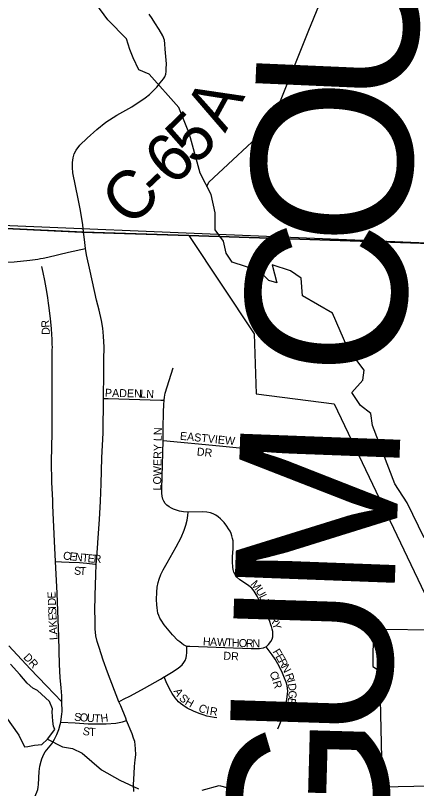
# Model space of a CAD drawing. Extents: x 0 to 34, y 0 to 22.
# Drawn here: x 28.055 to 28.529, y 17.603 to 18.518 of the extents above; entities that cross this region are included whole.
import ezdxf

# ---------------------------------------------------------------- set-up
doc = ezdxf.new("R2010")
doc.units = 0
for name, color, linetype in [('GM_X_Adjacent_County_Text', 7, 'Continuous'), ('GM_X_City_Street', 7, 'Continuous'), ('GM_X_City_Street_Text', 7, 'Continuous'), ('GM_X_Corporation', 7, 'Continuous'), ('GM_X_County_Road', 7, 'Continuous'), ('GM_X_County_Road_Text', 7, 'Continuous'), ('GM_X_Minor_Lake', 7, 'Continuous'), ('GM_X_Minor_River', 7, 'Continuous'), ('GM_X_Section', 7, 'Continuous'), ('GM_X_Township', 7, 'Continuous')]:
    doc.layers.add(name, color=color, linetype=linetype)

msp = doc.modelspace()

# ---------------------------------------------------------------- linework, layer by layer
at = {"layer": 'GM_X_City_Street'}
for points in [[(27.85393, 18.26885), (27.85999, 18.26259), (27.86684, 18.25642), (27.8741, 18.25072), (27.88171, 18.24549), (27.8896, 18.24071), (27.89778, 18.23644), (27.90626, 18.23284), (27.91499, 18.22991), (27.92391, 18.22763), (27.93299, 18.22608), (27.94524, 18.22494), (27.96066, 18.22431), (27.9792, 18.22428), (28.01942, 18.22523), (28.03796, 18.22566), (28.05337, 18.22652), (28.0718, 18.22836), (28.0813, 18.22968), (28.08427, 18.23019), (28.08748, 18.23074), (28.09309, 18.23181), (28.1176, 18.23769), (28.13753, 18.24213)], [(28.13753, 18.24213), (28.13658, 18.25279), (28.13559, 18.25882), (28.13528, 18.2617), (28.13525, 18.26196)], [(28.1591, 18.06485), (28.15953, 18.09534), (28.15934, 18.11085), (28.15974, 18.12537), (28.15893, 18.13859), (28.15799, 18.14787), (28.15656, 18.157), (28.15384, 18.16906), (28.15076, 18.18108), (28.14329, 18.21545), (28.13871, 18.2345), (28.13753, 18.24213)], [(28.10223, 17.87166), (28.10111, 17.89576), (28.09914, 17.93789), (28.09898, 17.94406), (28.0979, 17.96572), (28.09748, 17.99015), (28.09807, 18.02394), (28.09809, 18.05482), (28.0982, 18.08581), (28.09804, 18.10076), (28.09832, 18.11939), (28.09835, 18.12246), (28.09842, 18.12546), (28.09837, 18.12854), (28.09812, 18.13469), (28.09725, 18.14707), (28.09606, 18.1594), (28.0943, 18.17461), (28.09392, 18.17766), (28.09346, 18.18065), (28.09307, 18.18368), (28.09261, 18.18665), (28.09119, 18.1956), (28.08941, 18.20449), (28.08753, 18.21364), (28.08613, 18.22077)], [(28.23069, 18.06269), (28.23126, 18.06636), (28.23209, 18.07086), (28.24146, 18.1011)], [(28.15047, 17.86851), (28.15069, 17.87214), (28.15174, 17.88763), (28.15262, 17.9), (28.15415, 17.92162), (28.15551, 17.9433), (28.15623, 17.96383), (28.15704, 17.99457), (28.15852, 18.02397), (28.1591, 18.06485)], [(28.1591, 18.06485), (28.16459, 18.06469), (28.22689, 18.0628), (28.23069, 18.06269)], [(28.22962, 18.01486), (28.22951, 18.02921), (28.23008, 18.04908), (28.23022, 18.05707), (28.23069, 18.06269)], [(28.25908, 17.93036), (28.25355, 17.93074), (28.24896, 17.93143), (28.24543, 17.9325), (28.2419, 17.93366), (28.23929, 17.93473), (28.2366, 17.93642), (28.23407, 17.93834), (28.232, 17.94041), (28.23038, 17.94302), (28.22923, 17.94554), (28.22859, 17.94915), (28.22812, 17.95265), (28.22799, 17.95783), (28.22962, 18.01486)], [(28.22962, 18.01486), (28.29644, 18.00867), (28.31193, 18.00729), (28.3273, 18.00563), (28.33336, 18.00471), (28.33749, 18.00352), (28.34191, 18.0018), (28.34388, 18.00136), (28.34606, 18.00109), (28.34775, 18.00141), (28.34882, 18.00203), (28.3496, 18.00285), (28.35008, 18.00392), (28.35023, 18.0049), (28.35001, 18.00591), (28.34983, 18.00634), (28.34941, 18.00687), (28.34854, 18.0075), (28.34713, 18.00797), (28.34533, 18.00809), (28.34343, 18.00793), (28.34142, 18.00749), (28.33912, 18.00656)], [(28.25768, 17.77141), (28.25535, 17.77232), (28.25363, 17.77323), (28.25162, 17.77473), (28.24932, 17.77656), (28.24707, 17.77853), (28.24064, 17.78511), (28.23257, 17.7946), (28.23067, 17.79706), (28.2272, 17.80222), (28.22572, 17.80495), (28.22447, 17.80778), (28.22344, 17.8107), (28.22277, 17.81373), (28.22232, 17.8168), (28.22192, 17.82071), (28.22165, 17.82691), (28.22203, 17.83539), (28.22256, 17.84157), (28.22358, 17.847), (28.22479, 17.85085), (28.22692, 17.85641), (28.22977, 17.86195), (28.23443, 17.87005), (28.24503, 17.88911), (28.25071, 17.90019), (28.25441, 17.90875), (28.2564, 17.91465), (28.25787, 17.9207), (28.2587, 17.92613), (28.25908, 17.93036)], [(28.35141, 17.7707), (28.3541, 17.77351), (28.35715, 17.77712), (28.35845, 17.77988), (28.35923, 17.7828), (28.35955, 17.78556), (28.35919, 17.78888), (28.3587, 17.79192), (28.35795, 17.79491), (28.35709, 17.79704), (28.35581, 17.80065), (28.35063, 17.81166), (28.34926, 17.81439), (28.34066, 17.83075), (28.33713, 17.83669), (28.3344, 17.84007), (28.33102, 17.84303), (28.32592, 17.84654), (28.32045, 17.8501), (28.3169, 17.8531), (28.31473, 17.85652), (28.31335, 17.85926), (28.31248, 17.86221), (28.31195, 17.86526), (28.31154, 17.87143), (28.31164, 17.87762), (28.31235, 17.88686), (28.31248, 17.89301), (28.31227, 17.89608), (28.31177, 17.89911), (28.31099, 17.90209), (28.30997, 17.90499), (28.30873, 17.90782), (28.30707, 17.91057), (28.30502, 17.91369), (28.30159, 17.91799), (28.29739, 17.92228), (28.29481, 17.92454), (28.29191, 17.92648), (28.2888, 17.92808), (28.28568, 17.92938), (28.28106, 17.93035), (28.27622, 17.93053), (28.25908, 17.93036)], [(28.10223, 17.87166), (28.10908, 17.8714), (28.11843, 17.87109), (28.13072, 17.87057), (28.1392, 17.86982), (28.14916, 17.86866), (28.15047, 17.86851)], [(28.10966, 17.70563), (28.10946, 17.71303), (28.10895, 17.72232), (28.1078, 17.73456), (28.1069, 17.74981), (28.10593, 17.78256), (28.10394, 17.83426), (28.10223, 17.87166)], [(28.17724, 17.70583), (28.16383, 17.74068), (28.1586, 17.75523), (28.1539, 17.76996), (28.15164, 17.7772), (28.15003, 17.78394), (28.14922, 17.79203), (28.14895, 17.8039), (28.1487, 17.81312), (28.14917, 17.83177), (28.14976, 17.85622), (28.15047, 17.86851)], [(28.04689, 17.77203), (28.0723, 17.7449), (28.09152, 17.72464), (28.10966, 17.70563)], [(28.23074, 17.73517), (28.23161, 17.73565), (28.23958, 17.74041), (28.24734, 17.74558), (28.24977, 17.74752), (28.25198, 17.74969), (28.2539, 17.75212), (28.25545, 17.7548), (28.25661, 17.75767), (28.25736, 17.76069), (28.25769, 17.76374), (28.25756, 17.76679), (28.25768, 17.77141)], [(28.35141, 17.7707), (28.34809, 17.76927), (28.3435, 17.76832), (28.33354, 17.76848), (28.26102, 17.77111), (28.25768, 17.77141)], [(28.36511, 17.67368), (28.3677, 17.67927), (28.3696, 17.68465), (28.37119, 17.69003), (28.3734, 17.69777), (28.37545, 17.70616), (28.3764, 17.7117), (28.37688, 17.71518), (28.37703, 17.71834), (28.37688, 17.7215), (28.37624, 17.72498), (28.37498, 17.7291), (28.37327, 17.73371), (28.37099, 17.73954), (28.36689, 17.74796), (28.36218, 17.75606), (28.35866, 17.76122), (28.35141, 17.7707)], [(28.17724, 17.70583), (28.1828, 17.70873), (28.19105, 17.71305), (28.20735, 17.72206), (28.22623, 17.73269), (28.23074, 17.73517)], [(28.29322, 17.68689), (28.28999, 17.68732), (28.28563, 17.68812), (28.28138, 17.68899), (28.27707, 17.69034), (28.27207, 17.69196), (28.26535, 17.69459), (28.25816, 17.69828), (28.25266, 17.70184), (28.25018, 17.70372), (28.24786, 17.70579), (28.24572, 17.70804), (28.24374, 17.71046), (28.24026, 17.71564), (28.23722, 17.72108), (28.23331, 17.72958), (28.23074, 17.73517)], [(28.10836, 17.68164), (28.10902, 17.68507), (28.10977, 17.69129), (28.10988, 17.69442), (28.10966, 17.70563)], [(28.18636, 17.68384), (28.18522, 17.68657), (28.17933, 17.70094), (28.17724, 17.70583)], [(28.10836, 17.68164), (28.12548, 17.68075), (28.14071, 17.6798), (28.1555, 17.67957), (28.16208, 17.67992), (28.1736, 17.68055), (28.18126, 17.68207), (28.18509, 17.6834), (28.18636, 17.68384)], [(28.1948, 17.59947), (28.19439, 17.60772), (28.19521, 17.62113), (28.19576, 17.62935), (28.19658, 17.63702), (28.19713, 17.64317), (28.19699, 17.65002), (28.19658, 17.65481), (28.1959, 17.65892), (28.19465, 17.66293), (28.19303, 17.66795), (28.18636, 17.68384)], [(28.07178, 17.58311), (28.07451, 17.58769), (28.07636, 17.59097), (28.07876, 17.59615), (28.08008, 17.59897), (28.0811, 17.60192), (28.08181, 17.60495), (28.08217, 17.60803), (28.08297, 17.62338), (28.08373, 17.62944), (28.08501, 17.63543), (28.08591, 17.63834), (28.08703, 17.64116), (28.08841, 17.64386), (28.09005, 17.64643), (28.09382, 17.65128), (28.09768, 17.65622), (28.10103, 17.6615), (28.10387, 17.66708), (28.10611, 17.67292), (28.10784, 17.67893), (28.10836, 17.68164)]]:
    msp.add_lwpolyline(points, dxfattribs=at)
at = {"layer": 'GM_X_Corporation'}
msp.add_lwpolyline([(27.50706, 18.06564), (27.60948, 18.06256), (27.61116, 18.12049), (27.61116, 18.15798), (27.60564, 18.15628), (27.60565, 18.18117), (27.60524, 18.20728), (27.61083, 18.20833), (27.60953, 18.28012), (28.03523, 18.26605), (28.13337, 18.26149), (28.25997, 18.25738), (28.33724, 18.14128), (28.33966, 18.07033), (28.43214, 18.05835), (28.55968, 17.79037), (28.47825, 17.79119), (28.47781, 17.74759), (28.48568, 17.74233), (28.48869, 17.60507), (28.54513, 17.60631)], dxfattribs=at)
msp.add_lwpolyline([(27.50706, 18.06564), (27.60948, 18.06256), (27.61116, 18.12049), (27.61116, 18.15798), (27.60564, 18.15628), (27.60565, 18.18117), (27.60524, 18.20728), (27.61083, 18.20833), (27.60953, 18.28012), (28.03523, 18.26605), (28.13337, 18.26149), (28.25997, 18.25738), (28.33724, 18.14128), (28.33966, 18.07033), (28.43214, 18.05835), (28.55968, 17.79037), (28.47825, 17.79119), (28.47781, 17.74759), (28.48568, 17.74233), (28.48869, 17.60507), (28.54513, 17.60631)], dxfattribs=at)
at = {"layer": 'GM_X_County_Road'}
msp.add_lwpolyline([(28.13525, 18.26196), (28.13436, 18.27016), (28.13193, 18.28716), (28.12897, 18.30091), (28.12276, 18.33165), (28.12225, 18.33788), (28.12223, 18.34406), (28.12303, 18.34945), (28.12438, 18.35404), (28.12654, 18.35862), (28.13085, 18.36455), (28.13948, 18.37292), (28.1509, 18.38282), (28.16187, 18.39153), (28.17481, 18.39988), (28.19262, 18.40986), (28.20847, 18.42055), (28.21328, 18.42449), (28.21781, 18.42873), (28.22207, 18.43325), (28.22602, 18.43802), (28.22989, 18.44288), (28.23158, 18.44542), (28.23254, 18.44833), (28.233, 18.45144), (28.23325, 18.4546), (28.23342, 18.4608), (28.23199, 18.4781), (28.23172, 18.4843), (28.23118, 18.48888), (28.22929, 18.49401), (28.22472, 18.50133), (28.21975, 18.50911), (28.21645, 18.51432), (28.21313, 18.51954)], dxfattribs=at)
at = {"layer": 'GM_X_Minor_Lake'}
for points in [[(27.99403, 17.81025), (27.99061, 17.8125), (27.99142, 17.8053), (27.99374, 17.79924), (27.99454, 17.79355), (27.99385, 17.78482), (27.99051, 17.77568), (27.98792, 17.76769), (27.9846, 17.7559), (27.98197, 17.75246), (27.98578, 17.74945), (27.99074, 17.74493), (27.99799, 17.73815), (28.00866, 17.73101), (28.02012, 17.71781), (28.02814, 17.71066), (28.03428, 17.70007), (28.04347, 17.68799), (28.05879, 17.66646), (28.06533, 17.65246), (28.0695, 17.65287), (28.07745, 17.65444), (28.08615, 17.65527), (28.09255, 17.66176)], [(28.09255, 17.66176), (28.10156, 17.67284), (28.09963, 17.677), (28.09883, 17.68307), (28.09837, 17.69407), (28.09872, 17.69749), (28.09524, 17.7062), (28.08075, 17.719), (28.07542, 17.722), (28.06855, 17.72803), (28.06014, 17.73822), (28.04906, 17.75028)]]:
    msp.add_lwpolyline(points, dxfattribs=at)
at = {"layer": 'GM_X_Minor_River'}
for points in [[(28.28141, 18.31548), (28.28379, 18.32071), (28.35758, 18.38937), (28.40179, 18.50055), (28.42577, 18.55844), (28.43448, 18.59303), (28.44447, 18.61437), (28.45565, 18.62928), (28.46299, 18.65059), (28.46857, 18.695), (28.48617, 18.71225), (28.53638, 18.75754), (28.57229, 18.79508), (28.58827, 18.82217), (28.61736, 18.86153), (28.63021, 18.89845), (28.6331, 18.91061), (28.63749, 18.92468)], [(28.53832, 17.89997), (28.51821, 17.94108), (28.50359, 17.96367), (28.47713, 18.03277), (28.47547, 18.04678), (28.46326, 18.0565), (28.45288, 18.07193), (28.46597, 18.08648), (28.46736, 18.09825), (28.44817, 18.12382), (28.42995, 18.16571), (28.39455, 18.18618), (28.39281, 18.20701), (28.38024, 18.2156), (28.3586, 18.22294), (28.36412, 18.2014), (28.35463, 18.20433), (28.34279, 18.21595), (28.31128, 18.22584), (28.30398, 18.23676), (28.3008, 18.25075), (28.2912, 18.2643), (28.29099, 18.28439), (28.28622, 18.30595), (28.27347, 18.33121), (28.26087, 18.37733), (28.24805, 18.40904), (28.21283, 18.44847), (28.20067, 18.45364), (28.19409, 18.4676), (28.1902, 18.47779), (28.18628, 18.49026), (28.1641, 18.51277), (28.13992, 18.54587)], [(28.09255, 17.66176), (28.11043, 17.6524), (28.12219, 17.65059), (28.1336, 17.64497), (28.15648, 17.6254), (28.17818, 17.61303), (28.20023, 17.60293)], [(28.27565, 17.60119), (28.29569, 17.60665), (28.31544, 17.60148)]]:
    msp.add_lwpolyline(points, dxfattribs=at)
at = {"layer": 'GM_X_Section'}
msp.add_lwpolyline([(28.70052, 19.24223), (28.6651, 18.24345), (27.6773, 18.28453), (27.70209, 19.27644)], close=True, dxfattribs=at)
at = {"layer": 'GM_X_Township'}
for points in [[(26.64338, 18.32213), (26.64994, 18.32195), (26.65415, 18.32164), (26.6574, 18.3212), (26.66046, 18.32066), (26.66345, 18.31987), (26.93903, 18.30939), (27.3097, 18.29835), (27.60273, 18.28017), (27.85085, 18.27245), (28.03523, 18.26605), (28.13527, 18.2617), (28.25997, 18.25738), (28.66555, 18.2443), (28.72626, 19.93416)], [(28.59551, 16.41415), (28.59908, 16.58872), (28.59988, 16.61088), (28.63677, 17.49807), (28.63701, 17.50604), (28.6433, 17.85758), (28.66555, 18.2443), (28.25997, 18.25738), (28.13527, 18.2617), (28.03523, 18.26605), (27.85085, 18.27245), (27.60273, 18.28017), (27.3097, 18.29835), (26.93903, 18.30939), (26.66345, 18.31987), (26.66046, 18.32066), (26.6574, 18.3212), (26.65415, 18.32164), (26.64994, 18.32195), (26.64338, 18.32213)]]:
    msp.add_lwpolyline(points, dxfattribs=at)

# ---------------------------------------------------------------- texts
at = {"layer": 'GM_X_Adjacent_County_Text'}
for s, rotation, p in [('U', 87.49603, (28.52715, 18.41001)), ('O', 87.49603, (28.51983, 18.24267)), ('C', 87.50756, (28.51312, 18.08866)), ('M', 87.82797, (28.5029, 17.82581)), ('U', 88.17612, (28.49758, 17.6587)), ('G', 88.38934, (28.49288, 17.49145))]:
    msp.add_text(s, height=0.18939, rotation=rotation, dxfattribs=at).set_placement(p)
at = {"layer": 'GM_X_City_Street_Text'}
for s, rotation, p in [('R', 94.28275, (28.09519, 18.14889)), ('D', 91.52986, (28.09543, 18.14007)), ('PADEN', 358.75525, (28.16059, 18.06675)), ('LN', 356.98842, (28.20231, 18.06591)), ('LOWERY LN', 89.28359, (28.2271, 17.95586)), ('EASTVIEW', 354.36928, (28.24906, 18.01594)), ('DR', 353.98201, (28.26905, 17.99741)), ('C', 353.84483, (28.11075, 17.87427)), ('E', 353.82939, (28.1182, 17.87347)), ('N', 353.82395, (28.12483, 17.87275)), ('T', 353.86861, (28.13312, 17.87185)), ('E', 354.09465, (28.13979, 17.87114)), ('R', 358.15181, (28.14715, 17.8704)), ('S', 356.69289, (28.12386, 17.85635)), ('T', 357.06235, (28.13059, 17.85596)), ('M', 309.81491, (28.33249, 17.84477)), ('U', 299.94013, (28.33864, 17.83744)), ('E', 92.2404, (28.10239, 17.82819)), ('L', 296.27174, (28.34272, 17.83036)), ('D', 92.57975, (28.10276, 17.81988)), ('L', 294.5615, (28.33167, 17.81739)), ('B', 295.93522, (28.34567, 17.8244)), ('E', 295.84401, (28.34895, 17.81766)), ('I', 92.59392, (28.10295, 17.81572)), ('S', 92.56641, (28.10325, 17.80905)), ('N', 295.72377, (28.33452, 17.81114)), ('R', 295.89831, (28.35186, 17.81165)), ('E', 92.56908, (28.10355, 17.8024)), ('K', 92.57975, (28.10393, 17.79407)), ('R', 295.89831, (28.35513, 17.8049)), ('A', 92.59795, (28.10431, 17.78575)), ('Y', 287.67474, (28.35827, 17.79849)), ('L', 92.56908, (28.10461, 17.77908)), ('H', 357.52849, (28.27646, 17.77262)), ('A', 357.50665, (28.28478, 17.77226)), ('W', 357.53027, (28.29311, 17.77189)), ('T', 357.51567, (28.30393, 17.77143)), ('H', 357.51582, (28.31059, 17.77114)), ('O', 357.54973, (28.31892, 17.77077)), ('R', 358.09318, (28.32734, 17.77042)), ('N', 359.70024, (28.33513, 17.77016)), ('DR', 356.98842, (28.30063, 17.75569)), ('F', 300.85604, (28.35875, 17.76509)), ('DR', 312.88011, (28.06352, 17.75788)), ('E', 299.85332, (28.36214, 17.7594)), ('R', 298.79271, (28.36544, 17.75366)), ('N', 297.38602, (28.36902, 17.74714)), ('C', 290.07855, (28.35527, 17.73999)), ('R', 289.92502, (28.37362, 17.73771)), ('I', 288.69772, (28.35782, 17.73301)), ('R', 286.24564, (28.35913, 17.72916)), ('I', 286.48574, (28.37613, 17.7308)), ('A', 301.36118, (28.24164, 17.71839)), ('D', 276.26297, (28.37723, 17.72724)), ('S', 316.14751, (28.24764, 17.7092)), ('H', 330.77636, (28.25457, 17.70301)), ('E', 258.89365, (28.37788, 17.71138)), ('G', 268.03258, (28.37812, 17.71931)), ('C', 334.39052, (28.27038, 17.69534)), ('S', 355.59501, (28.12403, 17.68345)), ('O', 355.60297, (28.13067, 17.68294)), ('U', 355.60297, (28.13898, 17.6823)), ('H', 7.21203, (28.15604, 17.68139)), ('I', 350.24053, (28.27986, 17.69123)), ('R', 352.22763, (28.28432, 17.69047)), ('T', 357.25015, (28.14759, 17.68164)), ('S', 349.1186, (28.13377, 17.66699)), ('T', 359.60584, (28.14221, 17.66555))]:
    msp.add_text(s, height=0.00947, rotation=rotation, dxfattribs=at).set_placement(p)
at = {"layer": 'GM_X_County_Road_Text'}
for s, rotation, p in [('A', 61.31804, (28.30284, 18.37809)), ('5', 44.66076, (28.26713, 18.33913)), ('6', 43.7485, (28.24113, 18.31424)), ('C', 43.47092, (28.19013, 18.26585)), ('-', 43.53737, (28.22405, 18.29801))]:
    msp.add_text(s, height=0.05682, rotation=rotation, dxfattribs=at).set_placement(p)

doc.saveas('drawing.dxf')
